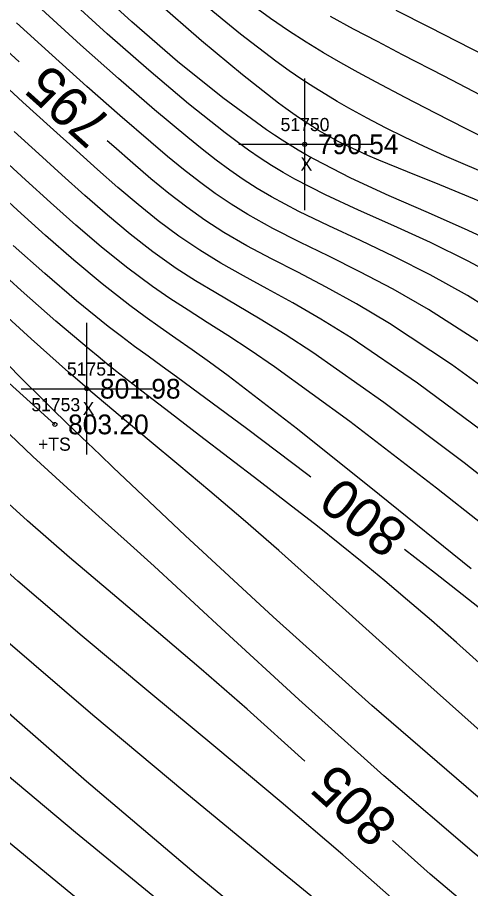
# Model space of a CAD drawing. Extents: x 1378535 to 1380697, y 997729 to 1000024.
# Drawn here: x 1379852.8 to 1379887.2, y 998667.4 to 998733.6 of the extents above; entities that cross this region are included whole.
import ezdxf

# ---------------------------------------------------------------- set-up
doc = ezdxf.new("R2010")
doc.units = 0
for name, color, linetype in [('RD_DTM_BkLn2', 7, 'Continuous'), ('RD_DTM_BkLn_txCode', 7, 'Continuous'), ('RD_DTM_Major1', 7, 'Continuous'), ('RD_DTM_Major1_Lbl', 7, 'Continuous'), ('RD_DTM_Minor1', 7, 'Continuous'), ('RD_EX_Misc', 7, 'Continuous'), ('RD_EX_Misc_txCode', 7, 'Continuous'), ('RD_EX_TX_Misc_ELEV', 7, 'Continuous'), ('RD_SMD_Locator', 7, 'Continuous')]:
    doc.layers.add(name, color=color, linetype=linetype)

msp = doc.modelspace()

# ---------------------------------------------------------------- linework, layer by layer
at = {"layer": 'RD_DTM_BkLn2'}
msp.add_lwpolyline([(1379855.611, 998702.628), (1379815.746, 998738.674), (1379770.168, 998788.836), (1379745.983, 998819.459), (1379725.877, 998843.791)], dxfattribs=at)
at = {"layer": 'RD_DTM_Major1'}
for points in [[(1379898.029, 998714.416), (1379895.831, 998715.737), (1379893.067, 998717.202), (1379890.271, 998718.531), (1379887.516, 998719.736), (1379884.878, 998720.827), (1379882.431, 998721.814), (1379880.248, 998722.71), (1379879.4, 998723.073), (1379878.603, 998723.431), (1379877.844, 998723.79), (1379877.11, 998724.161), (1379876.388, 998724.552), (1379875.665, 998724.972), (1379875.193, 998725.262), (1379874.711, 998725.571), (1379874.216, 998725.9), (1379873.704, 998726.254), (1379873.171, 998726.634), (1379872.614, 998727.044), (1379869.878, 998729.182), (1379866.755, 998731.786), (1379863.395, 998734.708)], [(1379852.883, 998730.183), (1379850.774, 998732.118)], [(1379890.793, 998703.529), (1379885.762, 998707.187), (1379881.063, 998710.294), (1379878.56, 998711.78), (1379876.237, 998713.059), (1379874.08, 998714.186), (1379872.072, 998715.219), (1379870.201, 998716.211), (1379868.452, 998717.22), (1379867.016, 998718.148), (1379865.633, 998719.135), (1379864.276, 998720.184), (1379862.917, 998721.301), (1379861.528, 998722.489), (1379860.082, 998723.754), (1379859.593, 998724.185)], [(1379875.072, 998698.622), (1379874.84, 998698.8), (1379870.187, 998702.315), (1379866.029, 998705.391), (1379864.863, 998706.238), (1379863.759, 998707.036), (1379862.702, 998707.803), (1379861.677, 998708.555), (1379860.671, 998709.307), (1379859.67, 998710.076), (1379857.266, 998712.021), (1379854.843, 998714.093), (1379852.439, 998716.234)], [(1379874.613, 998677.048), (1379870.239, 998680.991), (1379866.739, 998684.039), (1379863.325, 998686.941), (1379859.99, 998689.749), (1379856.728, 998692.515), (1379853.532, 998695.293), (1379850.396, 998698.135)], [(1379916.591, 998666.748), (1379915.338, 998667.408), (1379914.146, 998668.049), (1379913.004, 998668.688), (1379911.896, 998669.339), (1379910.81, 998670.017), (1379909.732, 998670.737), (1379908.116, 998671.909), (1379906.492, 998673.182), (1379904.863, 998674.529), (1379903.232, 998675.924), (1379901.604, 998677.343), (1379899.98, 998678.758), (1379898.948, 998679.649), (1379897.897, 998680.545), (1379896.805, 998681.466), (1379895.649, 998682.428), (1379894.407, 998683.449), (1379893.057, 998684.548), (1379889.097, 998687.719), (1379884.563, 998691.292), (1379882.2, 998693.128)], [(1379910.864, 998630.424), (1379908.874, 998631.363), (1379903.164, 998634.105), (1379900.423, 998635.459), (1379897.914, 998636.745), (1379895.557, 998638.017), (1379893.272, 998639.329), (1379890.98, 998640.735), (1379888.602, 998642.29), (1379884.305, 998645.297), (1379879.654, 998648.75), (1379874.757, 998652.53), (1379869.721, 998656.52), (1379864.655, 998660.603), (1379859.665, 998664.661), (1379855.403, 998668.141), (1379851.326, 998671.485)], [(1379968.401, 998622.953), (1379968.283, 998623.001), (1379964.025, 998624.785), (1379959.868, 998626.596), (1379955.869, 998628.42), (1379952.555, 998630.006), (1379949.328, 998631.6), (1379946.115, 998633.212), (1379942.842, 998634.849), (1379939.437, 998636.521), (1379935.825, 998638.235), (1379930.385, 998640.706), (1379924.548, 998643.321), (1379918.458, 998646.125), (1379912.258, 998649.163), (1379906.091, 998652.48), (1379900.102, 998656.123), (1379894.518, 998660.023), (1379889.214, 998664.167), (1379884.162, 998668.447), (1379881.287, 998671.01)]]:
    msp.add_lwpolyline(points, dxfattribs=at)
at = {"layer": 'RD_DTM_Minor1'}
for points in [[(1379890.065, 998715.975), (1379887.035, 998717.376), (1379884.013, 998718.695), (1379881.031, 998719.993), (1379878.122, 998721.334), (1379875.32, 998722.781), (1379874.712, 998723.124), (1379874.109, 998723.478), (1379873.508, 998723.843), (1379872.907, 998724.22), (1379872.303, 998724.612), (1379871.695, 998725.02), (1379868.377, 998727.435), (1379864.941, 998730.21), (1379861.469, 998733.225), (1379858.044, 998736.364)], [(1379889.982, 998713.464), (1379887.046, 998715.041), (1379884.167, 998716.44), (1379881.377, 998717.711), (1379878.709, 998718.905), (1379876.195, 998720.072), (1379873.87, 998721.263), (1379872.963, 998721.778), (1379872.082, 998722.313), (1379871.213, 998722.873), (1379870.343, 998723.467), (1379869.46, 998724.1), (1379868.551, 998724.78), (1379865.762, 998726.993), (1379862.747, 998729.539), (1379859.599, 998732.318), (1379856.411, 998735.232)], [(1379889.253, 998723.919), (1379886.899, 998725.096), (1379884.554, 998726.291), (1379882.257, 998727.482), (1379880.047, 998728.648), (1379878.681, 998729.383), (1379877.349, 998730.118), (1379876.034, 998730.875), (1379874.716, 998731.672), (1379873.379, 998732.531), (1379872.003, 998733.47), (1379869.392, 998735.402)], [(1379888.814, 998721.522), (1379886.848, 998722.351), (1379885.245, 998723.05), (1379883.7, 998723.75), (1379882.208, 998724.456), (1379880.761, 998725.173), (1379879.35, 998725.906), (1379877.968, 998726.661), (1379877.086, 998727.164), (1379876.203, 998727.689), (1379875.305, 998728.246), (1379874.383, 998728.847), (1379873.424, 998729.502), (1379872.418, 998730.221), (1379869.72, 998732.284), (1379866.776, 998734.69)], [(1379890.877, 998709.991), (1379886.978, 998712.433), (1379884.152, 998714), (1379881.441, 998715.371), (1379878.862, 998716.595), (1379876.433, 998717.726), (1379874.171, 998718.814), (1379872.093, 998719.911), (1379870.995, 998720.558), (1379869.941, 998721.235), (1379868.907, 998721.95), (1379867.872, 998722.714), (1379866.813, 998723.535), (1379865.709, 998724.425), (1379863.183, 998726.532), (1379860.436, 998728.909), (1379857.548, 998731.48), (1379854.598, 998734.172)], [(1379888.548, 998727.347), (1379885.222, 998729.08), (1379882.055, 998730.724), (1379880.145, 998731.716), (1379878.328, 998732.673), (1379876.581, 998733.624)], [(1379888.327, 998730.63), (1379884.122, 998732.79), (1379881.574, 998734.084)], [(1379888.325, 998708.597), (1379884.011, 998711.371), (1379881.332, 998712.906), (1379878.809, 998714.234), (1379876.442, 998715.411), (1379874.23, 998716.489), (1379872.174, 998717.524), (1379870.273, 998718.57), (1379869.004, 998719.353), (1379867.787, 998720.179), (1379866.596, 998721.055), (1379865.402, 998721.991), (1379864.179, 998722.996), (1379862.899, 998724.079), (1379860.56, 998726.095), (1379858.041, 998728.31), (1379855.401, 998730.676), (1379852.701, 998733.143)], [(1379888.759, 998701.636), (1379883.197, 998705.754), (1379878.132, 998709.203), (1379875.825, 998710.629), (1379873.708, 998711.855), (1379871.755, 998712.936), (1379869.942, 998713.928), (1379868.243, 998714.885), (1379866.633, 998715.862), (1379865.03, 998716.946), (1379863.473, 998718.106), (1379861.941, 998719.339), (1379860.409, 998720.642), (1379858.855, 998722.011), (1379857.257, 998723.443), (1379855.254, 998725.241), (1379853.174, 998727.116), (1379851.039, 998729.062)], [(1379893.081, 998694.709), (1379886.727, 998699.704), (1379880.635, 998704.297), (1379875.222, 998708.101), (1379873.128, 998709.453), (1379871.221, 998710.623), (1379869.469, 998711.66), (1379867.841, 998712.616), (1379866.307, 998713.541), (1379864.836, 998714.485), (1379863.063, 998715.74), (1379861.324, 998717.09), (1379859.602, 998718.522), (1379857.883, 998720.024), (1379856.149, 998721.582), (1379854.386, 998723.185), (1379852.522, 998724.875)], [(1379891.585, 998692.303), (1379884.639, 998697.787), (1379878.044, 998702.847), (1379872.311, 998707.01), (1379870.449, 998708.273), (1379868.755, 998709.379), (1379867.197, 998710.373), (1379865.743, 998711.298), (1379864.364, 998712.196), (1379863.026, 998713.11), (1379861.063, 998714.566), (1379859.12, 998716.13), (1379857.194, 998717.776), (1379855.28, 998719.48), (1379853.375, 998721.218), (1379851.475, 998722.964)], [(1379887.279, 998691.648), (1379880.296, 998697.271), (1379874.053, 998702.271), (1379868.799, 998706.317), (1379867.376, 998707.353), (1379866.054, 998708.29), (1379864.81, 998709.159), (1379863.622, 998709.989), (1379862.466, 998710.811), (1379861.319, 998711.654), (1379859.197, 998713.315), (1379857.051, 998715.106), (1379854.901, 998716.984), (1379852.765, 998718.907), (1379850.665, 998720.831)], [(1379889.381, 998683.168), (1379886.155, 998686.054), (1379884.248, 998687.726), (1379882.437, 998689.282), (1379880.692, 998690.751), (1379878.986, 998692.156), (1379877.29, 998693.526), (1379875.575, 998694.886), (1379873.374, 998696.605), (1379871.127, 998698.337), (1379868.86, 998700.072), (1379866.601, 998701.795), (1379864.376, 998703.496), (1379862.212, 998705.161), (1379861.548, 998705.675), (1379860.889, 998706.19), (1379860.23, 998706.709), (1379859.567, 998707.237), (1379858.897, 998707.778), (1379858.216, 998708.337), (1379855.688, 998710.482), (1379853.044, 998712.814), (1379850.367, 998715.238)], [(1379905.184, 998665.425), (1379899.809, 998669.39), (1379894.164, 998673.978), (1379888.437, 998678.914), (1379882.817, 998683.921), (1379877.493, 998688.723), (1379872.653, 998693.042), (1379869.922, 998695.412), (1379867.402, 998697.55), (1379865.04, 998699.523), (1379862.779, 998701.4), (1379860.564, 998703.248), (1379858.34, 998705.136), (1379857.504, 998705.859), (1379856.653, 998706.601), (1379853.798, 998709.138), (1379850.848, 998711.818)], [(1379934.126, 998646.594), (1379929.043, 998649.05), (1379924.776, 998651.013), (1379920.607, 998652.909), (1379916.447, 998654.875), (1379912.205, 998657.047), (1379907.792, 998659.56), (1379903.116, 998662.553), (1379895.562, 998668.057), (1379887.623, 998674.454), (1379879.701, 998681.264), (1379872.198, 998688.004), (1379865.515, 998694.195), (1379860.053, 998699.355), (1379859.043, 998700.317), (1379858.101, 998701.216), (1379857.215, 998702.065), (1379856.373, 998702.876), (1379855.563, 998703.662), (1379854.773, 998704.435), (1379852.961, 998706.231), (1379851.188, 998708.012)], [(1379936.86, 998641.524), (1379932.492, 998643.61), (1379927.619, 998645.822), (1379922.643, 998648.05), (1379917.554, 998650.408), (1379912.343, 998653.01), (1379907.002, 998655.971), (1379901.521, 998659.406), (1379894.519, 998664.432), (1379887.489, 998670.045), (1379880.635, 998675.919), (1379874.16, 998681.728), (1379868.267, 998687.145), (1379863.16, 998691.845), (1379861.102, 998693.707), (1379859.204, 998695.408), (1379857.414, 998697.013), (1379855.679, 998698.587), (1379853.945, 998700.194), (1379852.162, 998701.898)], [(1379951.793, 998626.801), (1379949.316, 998627.984), (1379946.898, 998629.156), (1379944.444, 998630.348), (1379941.858, 998631.591), (1379939.046, 998632.914), (1379933.079, 998635.632), (1379926.354, 998638.666), (1379919.216, 998641.956), (1379912.012, 998645.44), (1379905.086, 998649.058), (1379898.786, 998652.75), (1379894.724, 998655.472), (1379891.048, 998658.222), (1379887.624, 998661.02), (1379884.316, 998663.889), (1379880.991, 998666.849), (1379877.513, 998669.922), (1379872.829, 998673.926), (1379867.858, 998678.073), (1379862.756, 998682.298), (1379857.683, 998686.536), (1379852.796, 998690.722), (1379848.254, 998694.791)], [(1379944.074, 998626.769), (1379942.092, 998627.675), (1379935.489, 998630.659), (1379927.845, 998634.121), (1379919.702, 998637.882), (1379911.604, 998641.765), (1379904.092, 998645.592), (1379897.711, 998649.183), (1379895.238, 998650.746), (1379893.023, 998652.269), (1379890.959, 998653.803), (1379888.936, 998655.401), (1379886.848, 998657.112), (1379884.586, 998658.989), (1379878.95, 998663.626), (1379872.45, 998668.954), (1379865.495, 998674.689), (1379858.496, 998680.546), (1379851.863, 998686.241)], [(1379938.267, 998625.507), (1379929.989, 998629.234), (1379921.044, 998633.351), (1379912.145, 998637.56), (1379904.004, 998641.558), (1379897.335, 998645.048), (1379896.697, 998645.401), (1379896.086, 998645.745), (1379895.497, 998646.083), (1379894.928, 998646.416), (1379894.375, 998646.746), (1379893.836, 998647.074), (1379892.958, 998647.625), (1379892.095, 998648.188), (1379891.229, 998648.772), (1379890.346, 998649.388), (1379889.429, 998650.044), (1379888.462, 998650.751), (1379882.191, 998655.55), (1379874.612, 998661.617), (1379866.346, 998668.436), (1379858.012, 998675.494), (1379850.229, 998682.278)], [(1379929.152, 998625.794), (1379921.177, 998629.571), (1379913.278, 998633.325), (1379906, 998636.821), (1379899.89, 998639.828), (1379898.019, 998640.779), (1379896.342, 998641.656), (1379894.816, 998642.485), (1379893.399, 998643.294), (1379892.05, 998644.108), (1379890.726, 998644.953), (1379888.483, 998646.487), (1379886.145, 998648.199), (1379883.662, 998650.108), (1379880.983, 998652.233), (1379878.061, 998654.594), (1379874.845, 998657.209), (1379869.34, 998661.684), (1379863.349, 998666.565), (1379857.188, 998671.623), (1379851.171, 998676.629)]]:
    msp.add_lwpolyline(points, dxfattribs=at)
at = {"layer": 'RD_EX_Misc'}
for p, q in [((1379874.608, 998718.916), (1379874.608, 998728.916)), ((1379869.608, 998723.916), (1379879.608, 998723.916)), ((1379858.037, 998700.34), (1379858.037, 998710.34)), ((1379853.037, 998705.34), (1379863.037, 998705.34))]:
    msp.add_line(p, q, dxfattribs=at)
at = {"layer": 'RD_SMD_Locator'}
for centre in [(1379874.608, 998723.916), (1379858.037, 998705.34), (1379855.611, 998702.628)]:
    msp.add_circle(centre, 0.15, dxfattribs=at)

# ---------------------------------------------------------------- texts
at = {"layer": 'RD_DTM_BkLn_txCode'}
for s, p in [('51753', (1379853.816, 998703.628)), ('+TS', (1379854.328, 998700.628))]:
    msp.add_text(s, height=1, dxfattribs=at).set_placement(p)
at = {"layer": 'RD_DTM_Major1_Lbl'}
for s, rotation, p in [('795', 138.20371, (1379860.131, 998725.69)), ('800', 142.37988, (1379882.645, 998694.692)), ('805', 137.85873, (1379881.838, 998672.516))]:
    msp.add_text(s, height=3, rotation=rotation, dxfattribs=at).set_placement(p)
at = {"layer": 'RD_EX_Misc_txCode'}
for s, p in [('51750', (1379872.773, 998724.916)), ('X', (1379874.293, 998721.916)), ('51751', (1379856.525, 998706.34)), ('X', (1379857.722, 998703.34))]:
    msp.add_text(s, height=1, dxfattribs=at).set_placement(p)
at = {"layer": 'RD_EX_TX_Misc_ELEV'}
for s, p in [('790.54', (1379875.608, 998723.166)), ('801.98', (1379859.037, 998704.59)), ('803.20', (1379856.611, 998701.878))]:
    msp.add_text(s, height=1.5, dxfattribs=at).set_placement(p)

doc.saveas('drawing.dxf')
